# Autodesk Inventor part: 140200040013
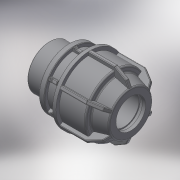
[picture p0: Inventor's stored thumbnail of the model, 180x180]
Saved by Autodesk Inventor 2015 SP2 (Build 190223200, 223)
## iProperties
Created: 2017-08
Part Number: 140200040013
Material: Generic
Description: PLASSON L.14 MALE ADAPTOR (SILVER) 40-1.1/4''
Document SubType Name: Modeling
Designer: KIM
Density: 1 g/cm^3
Appearance: Default
Author: KIM
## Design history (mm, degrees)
derived "140200.ipt"
feature "Solid1::140200.ipt"
tag "TaggingFeature1"
body "Solid1"
other parameters: "d2" = 73, "d4" = 15 deg, "d5" = 48.18, "d6" = 15.8994, "d10" = 73, "d16" = 40.8, "d17" = 3.65, "d18" = 99, "d19" = 6, "d21" = 6, "d22" = 50.292, "d24" = 3.65, "d25" = 65.7, "d26" = 54.75, "d27" = 3.65, "d28" = 135 deg, "d29" = 2.19, "d31" = 2, "d44" = 0.8, "d45" = 1.2, "d46" = 150 deg, "d49" = 3.65, "d50" = 0, "d51" = 2.19, "d52" = 1.46, "d53" = 45 deg, "d54" = 21, "d55" = 8.4, "d56" = 3.65, "d57" = 0, "d58" = 1.2, "d59" = 0.8, "d61" = 360 deg, "d63" = 41.91, "d64" = 32, "d66" = 56.5785, "R_" = 41.91, "E_" = 73, "H_" = 99, "l_" = 73
